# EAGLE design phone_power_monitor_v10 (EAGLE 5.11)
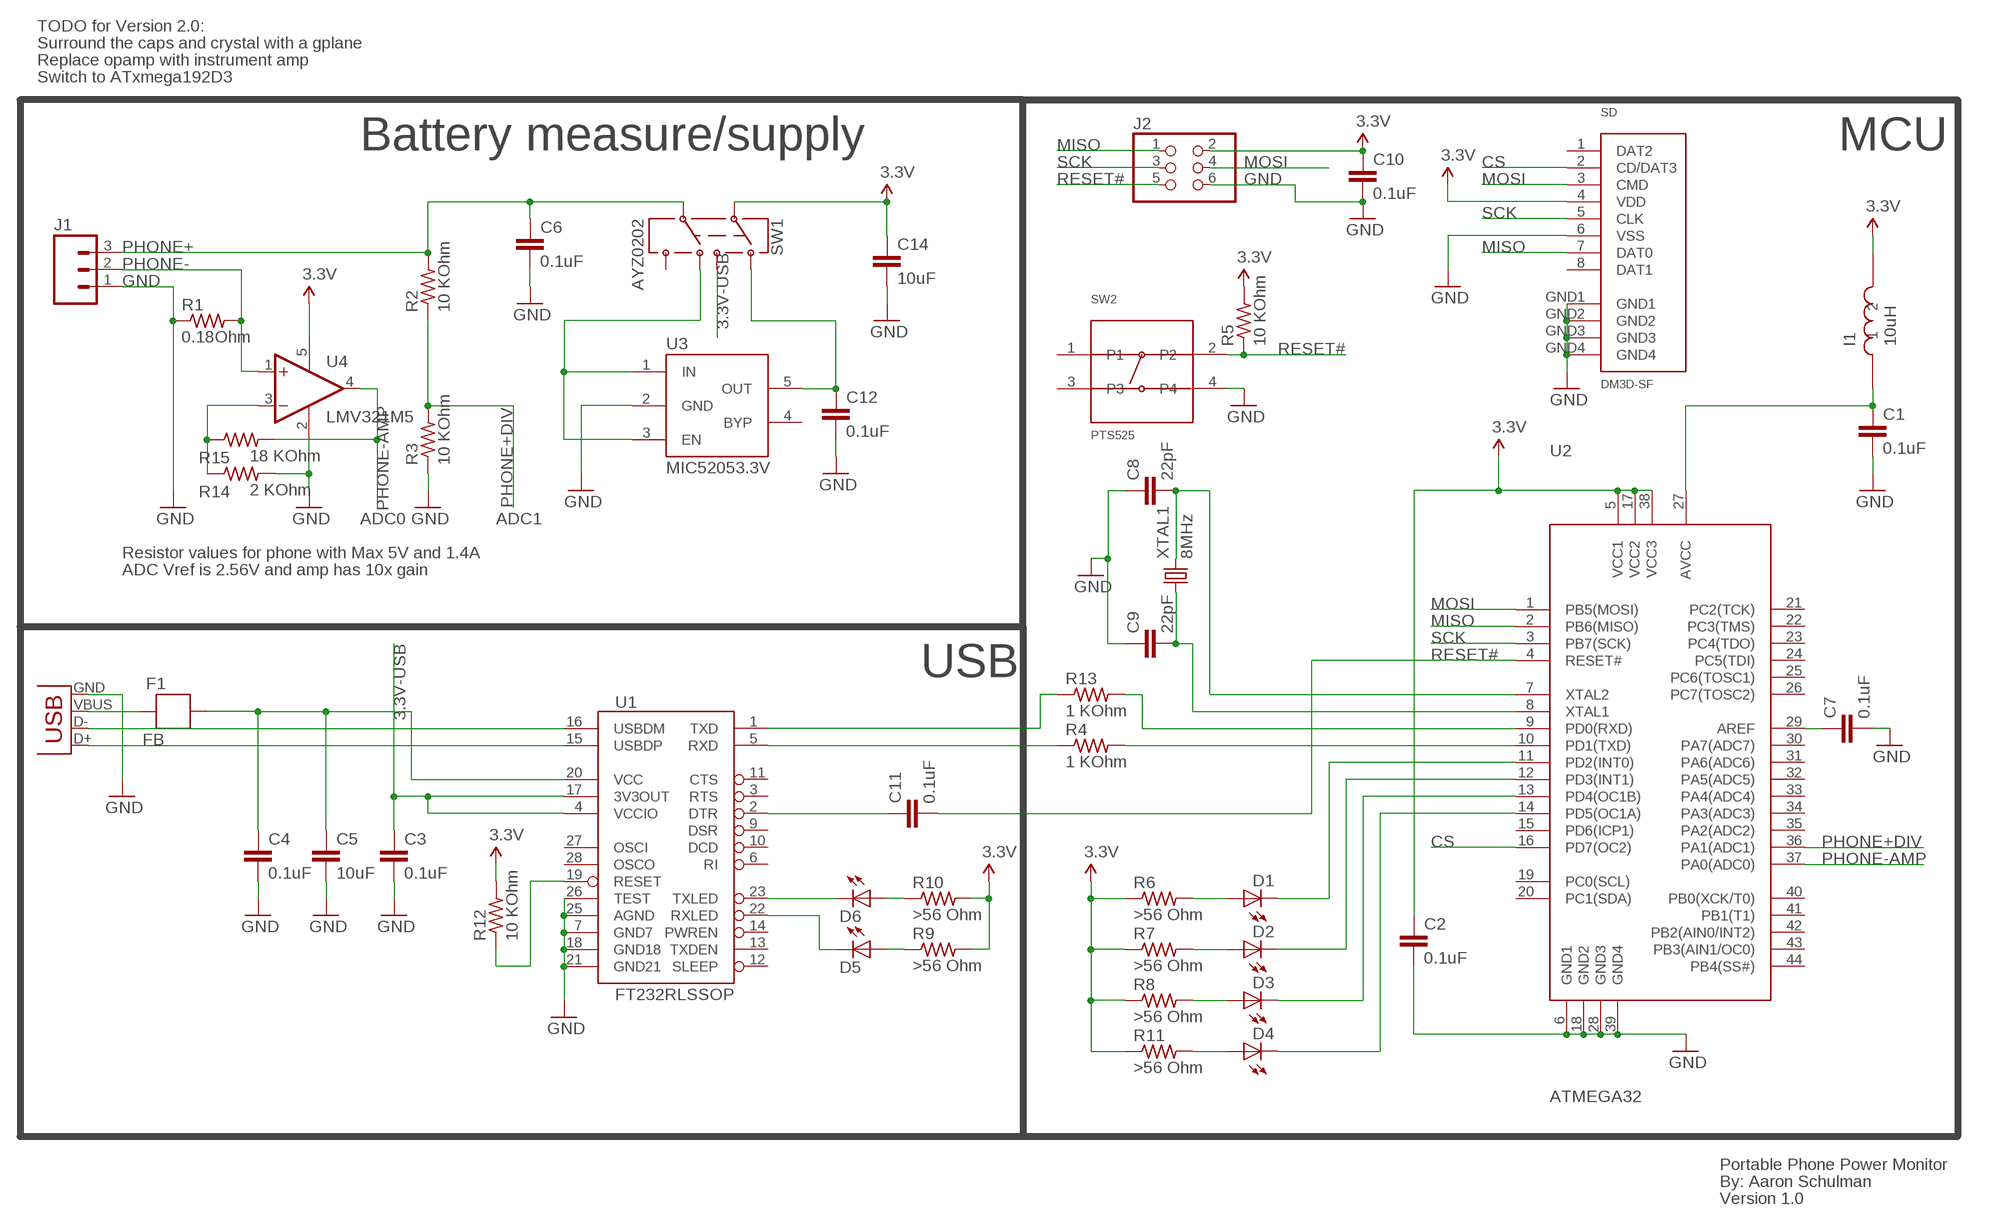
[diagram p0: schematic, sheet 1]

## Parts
C1  0.1uF  CAP0603-CAP  [0603-CAP]
C2  0.1uF  CAP0603-CAP  [0603-CAP]
C3  0.1uF  CAP0603-CAP  [0603-CAP]
C4  0.1uF  CAP0603-CAP  [0603-CAP]
C5  10uF  CAP0603-CAP  [0603-CAP]
C6  0.1uF  CAP0603-CAP  [0603-CAP]
C7  0.1uF  CAP0603-CAP  [0603-CAP]
C8  22pF  CAP0603-CAP  [0603-CAP]
C9  22pF  CAP0603-CAP  [0603-CAP]
C10  0.1uF  CAP0603-CAP  [0603-CAP]
C11  0.1uF  CAP0603-CAP  [0603-CAP]
C12  0.1uF  CAP0603-CAP  [0603-CAP]
C14  10uF  CAP0603-CAP  [0603-CAP]
D1  LED0603  [LED-0603]
D2  LED0603  [LED-0603]
D3  LED0603  [LED-0603]
D4  LED0603  [LED-0603]
D5  LED0603  [LED-0603]
D6  LED0603  [LED-0603]
F1  FB  [0603]
I1  10uH  IHLP-2020CZ-11  [IHLP-2020CZ-11]
J1  M03PTH  [1X03]
J2  PINHD-2X3  [2X03]
R1  0.18Ohm  R-US_R2512  [R2512]
R2  10 KOhm  R-US_R0603  [R0603]
R3  10 KOhm  R-US_R0603  [R0603]
R4  1 KOhm  R-US_R0603  [R0603]
R5  10 KOhm  R-US_R0603  [R0603]
R6  >56 Ohm  R-US_R0603  [R0603]
R7  >56 Ohm  R-US_R0603  [R0603]
R8  >56 Ohm  R-US_R0603  [R0603]
R9  >56 Ohm  R-US_R0603  [R0603]
R10  >56 Ohm  R-US_R0603  [R0603]
R11  >56 Ohm  R-US_R0603  [R0603]
R12  10 KOhm  R-US_R0603  [R0603]
R13  1 KOhm  R-US_R0603  [R0603]
R14  2 KOhm  R-US_R0603  [R0603]
R15  18 KOhm  R-US_R0603  [R0603]
SD  DM3D-SF  [DM3D-SF]
SW1  AYZ0202  [AYZ0202]
SW2  PTS525  [PT525]
U1  FT232RLSSOP  [SSOP28DB]
U2  ATMEGA32  [TQFP-44]
U3  MIC52053.3V  [SOT23-5]
U4  LMV321M5  [SOT23-5]
X1  USBSMD  [USB-MINIB]
XTAL1  8MHz  CRYSTAL10.5X4.8  [CRYSTAL-SMD-10.5X4.8-2PIN]

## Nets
3.3V: C2.1 C10.1 C14.1 I1.2 J2.2 R5.2 R6.1 R7.1 R8.1 R9.2 R10.2 R11.1 R12.2 SD.4(VDD) SW1.2 U2.5(VCC1) U2.17(VCC2) U2.38(VCC3) U4.5(V+)
3.3V-USB: C3.1 SW1.1 U1.4(VCCIO) U1.17(3V3OUT)
CS: SD.2(CD/DAT3) U2.16(PD7(OC2))
D4: D4.C U2.14(PD5(OC1A))
GND: C1.2 C2.2 C3.2 C4.2 C5.2 C6.2 C7.2 C8.1 C9.1 C10.2 C12.2 C14.2 J1.1 J2.6 R1.1 R3.1 R14.2 SD.6(VSS) SD.GND1 SD.GND2 SD.GND3 SD.GND4 SW2.4 U1.7(GND7) U1.18(GND18) U1.21(GND21) U1.25(AGND) U1.26(TEST) U2.6(GND1) U2.18(GND2) U2.28(GND3) U2.39(GND4) U3.2(GND) U4.2(V-) X1.GND
MISO: J2.1 SD.7(DAT0) U2.2(PB6(MISO))
MOSI: J2.4 SD.3(CMD) U2.1(PB5(MOSI))
N$1: C8.2 U2.7(XTAL2) XTAL1.P$2
N$2: C1.1 I1.1 U2.27(AVCC)
N$3: C7.1 U2.29(AREF)
N$4: R14.1 R15.1 U4.3(-IN)
N$5: C11.1 U1.2(DTR)
N$6: D1.A R6.2
N$7: F1.2 X1.VBUS
N$8: C4.1 C5.1 F1.1 U1.20(VCC)
N$9: C9.2 U2.8(XTAL1) XTAL1.P$1
N$10: R4.1 U1.5(RXD)
N$11: R4.2 U2.10(PD1(TXD))
N$12: R13.1 U1.1(TXD)
N$13: R13.2 U2.9(PD0(RXD))
N$14: C12.1 SW1.3 U3.5(OUT)
N$15: D6.C U1.23(TXLED)
N$16: D5.C U1.22(RXLED)
N$17: D2.A R7.2
N$18: D3.A R8.2
N$19: D1.C U2.11(PD2(INT0))
N$20: D4.A R11.2
N$21: D6.A R10.1
N$22: D2.C U2.12(PD3(INT1))
N$23: D3.C U2.13(PD4(OC1B))
N$25: D5.A R9.1
N$26: R12.1 U1.19(RESET)
PHONE+: C6.1 J1.3 R2.2 SW1.5
PHONE+DIV: R2.1 R3.2 U2.36(PA1(ADC1))
PHONE-: J1.2 R1.2 U4.1(+IN)
PHONE-AMP: R15.2 U2.37(PA0(ADC0)) U4.4(OUT)
RESET#: C11.2 J2.5 R5.1 SW2.2 U2.4(RESET#)
SCK: J2.3 SD.5(CLK) U2.3(PB7(SCK))
SWITCH_PHONE+: SW1.6 U3.1(IN) U3.3(EN)
USBDM: U1.16(USBDM) X1.D-
USBDP: U1.15(USBDP) X1.D+
Unconnected: SD.1(DAT2) SD.8(DAT1) SW1.4 SW2.1 SW2.3 U1.3(RTS) U1.6(RI) U1.9(DSR) U1.10(DCD) U1.11(CTS) U1.12(SLEEP) U1.13(TXDEN) U1.14(PWREN) U1.27(OSCI) U1.28(OSCO) U2.15(PD6(ICP1)) U2.19(PC0(SCL)) U2.20(PC1(SDA)) U2.21(PC2(TCK)) U2.22(PC3(TMS)) U2.23(PC4(TDO)) U2.24(PC5(TDI)) U2.25(PC6(TOSC1)) U2.26(PC7(TOSC2)) U2.30(PA7(ADC7)) U2.31(PA6(ADC6)) U2.32(PA5(ADC5)) U2.33(PA4(ADC4)) U2.34(PA3(ADC3)) U2.35(PA2(ADC2)) U2.40(PB0(XCK/T0)) U2.41(PB1(T1)) U2.42(PB2(AIN0/INT2)) U2.43(PB3(AIN1/OC0)) U2.44(PB4(SS#)) U3.4(BYP)

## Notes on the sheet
- TODO for Version 2.0:
- Surround the caps and crystal with a gplane
- Replace opamp with instrument amp
- Switch to ATxmega192D3
- Battery measure/supply | MCU
- ADC0 | ADC1
- Resistor values for phone with Max 5V and 1.4A
- ADC Vref is 2.56V and amp has 10x gain
- USB
- Portable Phone Power Monitor
- By: Aaron Schulman
- Version 1.0

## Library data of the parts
C1-C12 C14 = SparkFun:CAP: Capacitor
D1-D6 = SparkFun:LED: LEDs
F1 = SparkFun:FB
I1 = phone_power_monitor:IHLP-2020CZ-11
J1 = SparkFun:M03: Header 3 Standard 3-pin 0.1" header. Use with straight break away headers (SKU : PRT-00116), right angle break away headers (PRT-00553), swiss pins (PRT-00743), machine pins (PRT-00117), and female headers (PRT-00115). Molex polarized connector foot print use with SKU : PRT-08232 with associated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
J2 = SparkFun:PINHD-2X3: PIN HEADER
R1 = resistor:R-US_: RESISTOR, American symbol
R2-R15 = rcl:R-US_: RESISTOR, American symbol
SD = phone_power_monitor:DM3D-SF
SW1 = SparkFun:AYZ0202: SPDT Slide Switch Simple SMD single-pull double-throw slide switch. Good for less than 350mA power switch, switching UARTs between devices, etc. Spark Fun Electronics SKU : COM-00597
SW2 = phone_power_monitor:PTS525
U1 = SparkFun:FT232RL: USB UART FT232RL 4th Generation USB UART (USB <-> Serial) Controller. Spark Fun Electronics SKU : COM-00650
U2 = phone_power_monitor:ATMEGA32
U3 = phone_power_monitor:MIC5205
U4 = linear:LMV321?*: General Purpose, Low Voltage, Rail-to-Rail Output Operational Amplifiers Source: http://www.national.com/mpf/LM/LMV321.html http://www.national.com/dt/lmv_qual.pdf
X1 = SparkFun:USB: USB Connectors USB-B-PTH is fully proven SKU : PRT-00139 USB-miniB is fully proven SKU : PRT-00587 USB-A-PCB is untested. USB-A-H is throughly reviewed, but untested. Spark Fun Electronics SKU : PRT-00437 USB-B-SMT is throughly reviewed, but untested. Needs silkscreen touching up. USB-A-S has not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
XTAL1 = SparkFun:CRYSTAL: Crystals

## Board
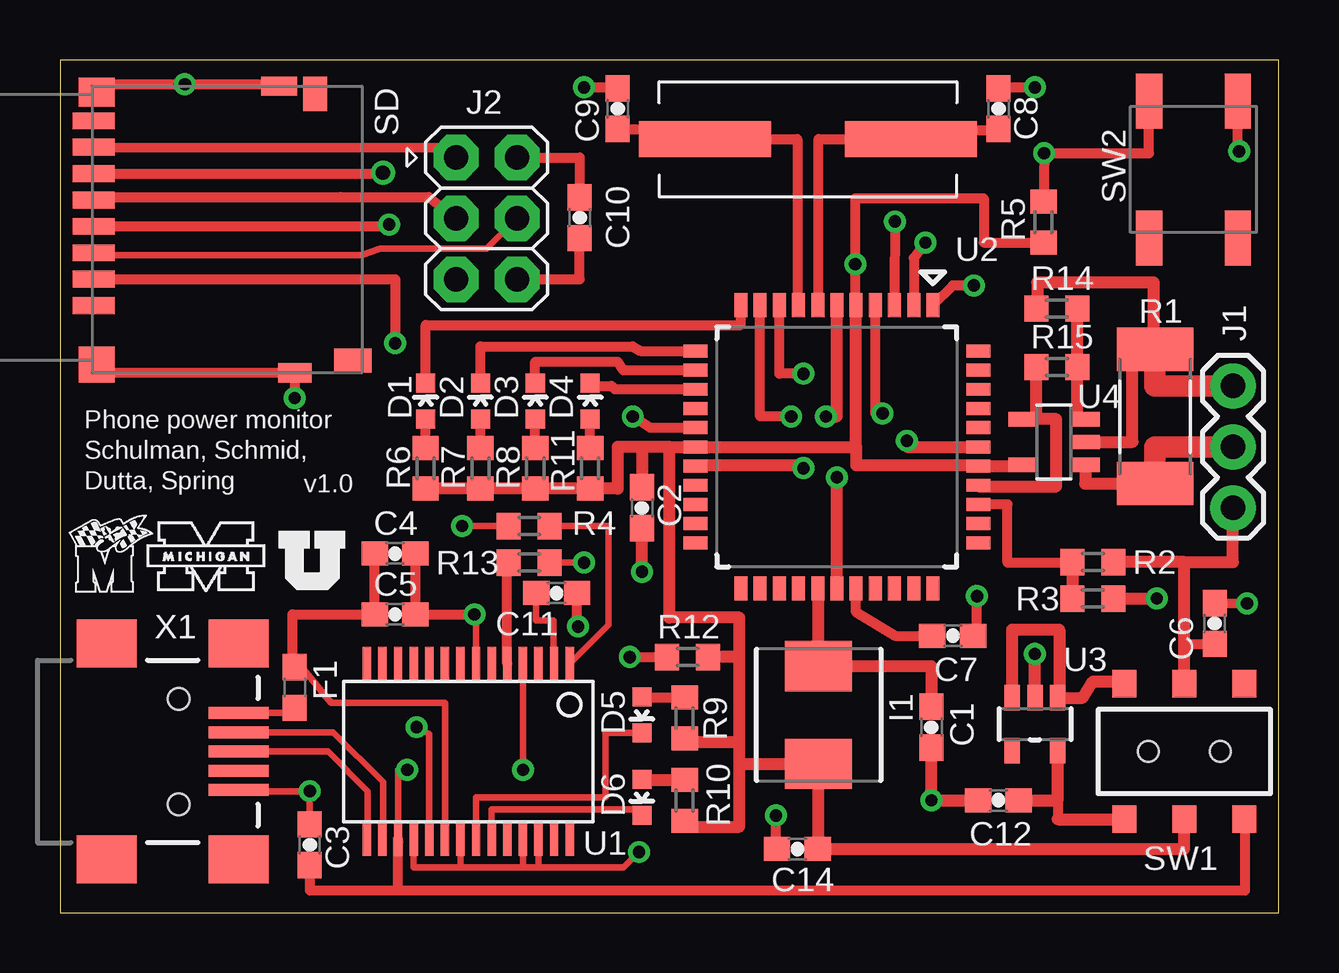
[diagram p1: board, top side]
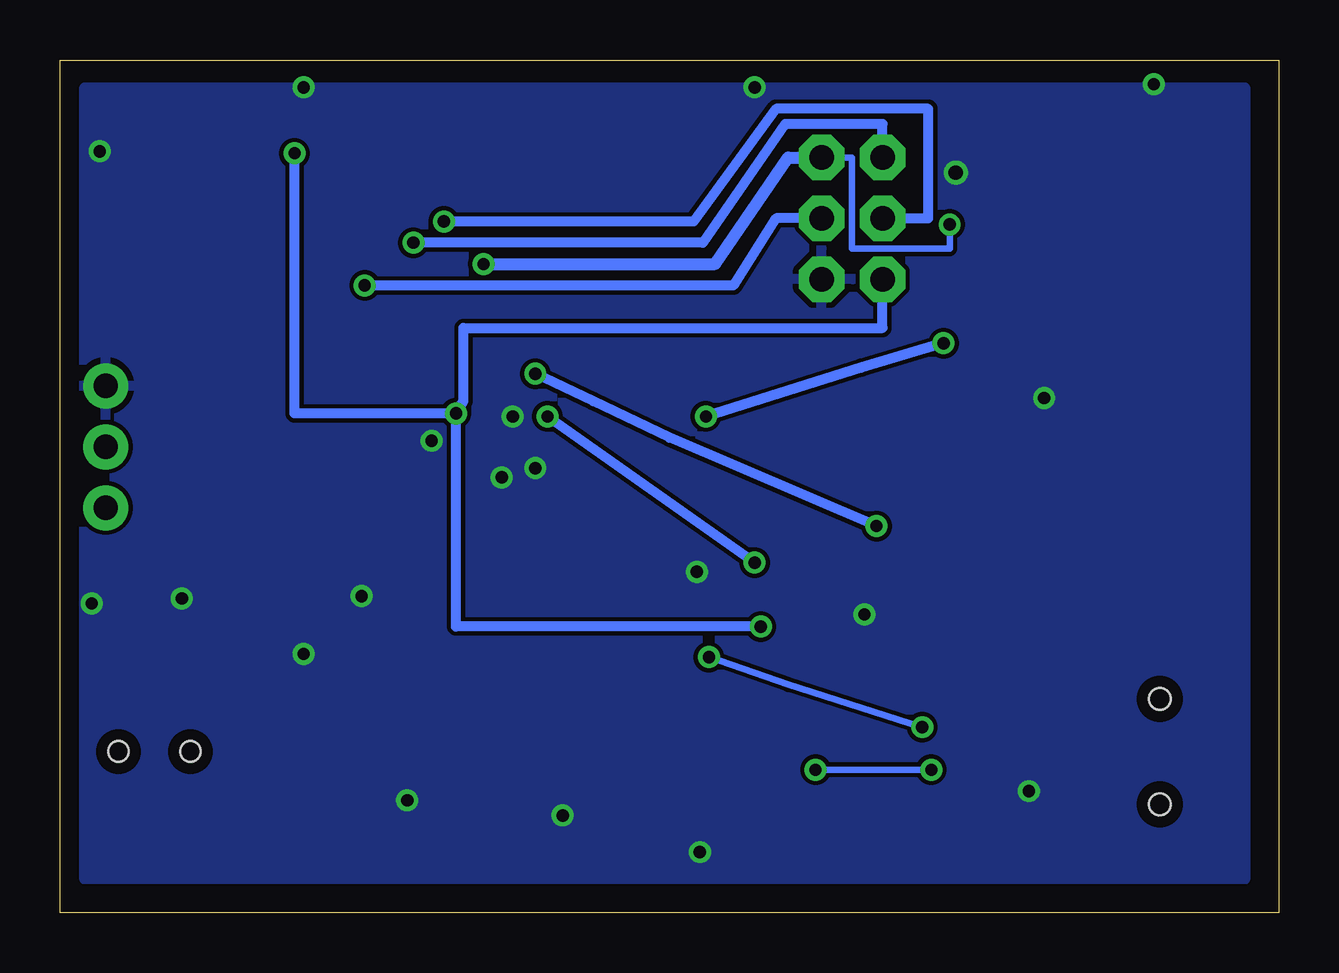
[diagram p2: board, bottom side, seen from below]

Size 50.8 x 35.56 mm. Coordinates in mm from the lower left corner, seen from the top.
Outline: 0,0 50.8,0 50.8,35.56 0,35.56 0,0
Copper layers (1*16): Top 0.0178mm / dielectric 1.4986mm / Bottom 0.0178mm
Design rules "SSC-EAGLE-2Lyr_v1.0.0.3 *": minimum track width 6mil, minimum drill 14mil, track to track 7mil, track to pad 7mil, pad to pad 7mil, via to via 7mil, smd to smd 7mil, copper to edge 20mil, drill to drill 16mil, minimum pad ring 8mil, minimum via ring 8mil, stop-mask expansion 3mil, vias tented up to drill 0mil, thermal gap 10mil

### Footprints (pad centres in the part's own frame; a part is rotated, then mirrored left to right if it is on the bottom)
0603-CAP = smd 1.1 x 1: 1 -0.85,0; 2 0.85,0
LED-0603 = smd 0.8 x 0.8: A 0,-0.75; C 0,0.75
0603 = smd 1.1 x 1: 1 -0.85,0; 2 0.85,0
IHLP-2020CZ-11 = smd 2.1 x 2.79: 1 -2.038,0; 2 2.038,0
1X03 = drill 1.016 pad 1.88 round: 1 0,0; 2 2.54,0; 3 5.08,0
2X03 = drill 1.016 pad 1.88 octagon: 1 -2.54,-1.27; 2 -2.54,1.27; 3 0,-1.27; 4 0,1.27; 5 2.54,-1.27; 6 2.54,1.27
R2512 = smd 1.8 x 3.2: 1 -2.8,0; 2 2.8,0
R0603 = smd 1 x 1.1: 1 -0.85,0; 2 0.85,0
DM3D-SF = smd 0.7 x 1.75: 1 7.7,-0.875; 2 6.6,-0.875; 3 5.5,-0.875; 4 4.4,-0.875; 5 3.3,-0.875; 6 2.2,-0.875; 7 1.1,-0.875; 8 0,-0.875 | smd 0.8 x 1.5: GND1 -1.45,6.85 | smd 0.8 x 1.4: GND2 10.5,7.5 | smd 1.5 x 1.5: GND3 10.15,-0.75 | smd 1.2 x 1.5: GND4 -1.2,-0.75 | smd 1 x 1.55: P$4 10,9.925 | smd 1.45 x 1: P$5 -1.125,8.35
AYZ0202 = smd 1 x 1.15: 1 -2.5,2.825; 2 0,2.825; 3 2.5,2.825; 4 -2.5,-2.825; 5 0,-2.825; 6 2.5,-2.825 | hole 0.85: 1.5,0; -1.5,0
PT525 = smd 2.3 x 1.1: 1 -2.85,1.85; 2 2.85,1.85; 3 -2.85,-1.85; 4 2.85,-1.85
SSOP28DB = smd 0.348 x 1.397: 1 -4.225,-3.656; 2 -3.575,-3.656; 3 -2.925,-3.656; 4 -2.275,-3.656; 5 -1.625,-3.656; 6 -0.975,-3.656; 7 -0.325,-3.656; 8 0.325,-3.656; 9 0.975,-3.656; 10 1.625,-3.656; 11 2.275,-3.656; 12 2.925,-3.656; 13 3.575,-3.656; 14 4.225,-3.656; 15 4.225,3.656; 16 3.575,3.656; 17 2.925,3.656; 18 2.275,3.656; 19 1.625,3.656; 20 0.975,3.656; 21 0.325,3.656; 22 -0.325,3.656; 23 -0.975,3.656; 24 -1.625,3.656; 25 -2.275,3.656; 26 -2.925,3.656; 27 -3.575,3.656; 28 -4.225,3.656
TQFP-44 = smd 1 x 0.54: 1 -5.9,4; 2 -5.9,3.2; 3 -5.9,2.4; 4 -5.9,1.6; 5 -5.9,0.8; 6 -5.9,0; 7 -5.9,-0.8; 8 -5.9,-1.6; 9 -5.9,-2.4; 10 -5.9,-3.2; 11 -5.9,-4; 23 5.9,-4; 24 5.9,-3.2; 25 5.9,-2.4; 26 5.9,-1.6; 27 5.9,-0.8; 28 5.9,0; 29 5.9,0.8; 30 5.9,1.6; 31 5.9,2.4; 32 5.9,3.2; 33 5.9,4 | smd 0.54 x 1: 12 -4,-5.9; 13 -3.2,-5.9; 14 -2.4,-5.9; 15 -1.6,-5.9; 16 -0.8,-5.9; 17 0,-5.9; 18 0.8,-5.9; 19 1.6,-5.9; 20 2.4,-5.9; 21 3.2,-5.9; 22 4,-5.9; 34 4,5.9; 35 3.2,5.9; 36 2.4,5.9; 37 1.6,5.9; 38 0.8,5.9; 39 0,5.9; 40 -0.8,5.9; 41 -1.6,5.9; 42 -2.4,5.9; 43 -3.2,5.9; 44 -4,5.9
SOT23-5 = smd 0.65 x 1.06: 1 0.95,1.1; 2 0,1.1; 3 -0.95,1.1; 4 -0.95,-1.1; 5 0.95,-1.1
SOT23-5' = smd 0.6 x 1.2: 1 -0.95,-1.306; 2 0,-1.306; 3 0.95,-1.306; 4 0.95,1.306; 5 -0.95,1.306
USB-MINIB = smd 2.5 x 0.5: D+ 2.5,0; D- 2.5,0.8; GND 2.5,-1.6; ID 2.5,-0.8; VBUS 2.5,1.6 | smd 2.5 x 2: MTN1 -3,4.5; MTN2 2.5,4.5; MTN3 -3,-4.5; MTN4 2.5,-4.5 | hole 0.9: 0,2.2; 0,-2.2
CRYSTAL-SMD-10.5X4.8-2PIN = smd 5.5 x 1.5: P$1 -4.3,0; P$2 4.3,0

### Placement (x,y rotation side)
C1  36.32,7.75 270 top
C2  24.26,16.89 270 top
C3  10.41,2.84 90 top
C4  13.97,14.99 0 top
C5  13.97,12.45 0 top
C6  48.13,12.06 90 top
C7  37.21,11.56 0 top
C8  39.12,33.53 270 top
C9  23.24,33.53 270 top
C10  21.67,28.98 270 top
C11  20.7,13.34 0 top
C12  39.12,4.7 180 top
C14  30.73,2.67 180 top
D1  15.24,21.34 0 top
D2  17.53,21.34 0 top
D3  19.81,21.34 0 top
D4  22.1,21.34 0 top
D5  24.26,8.26 180 top
D6  24.26,4.83 180 top
F1  9.78,9.4 270 top
I1  31.62,8.26 270 top
J1  48.9,21.97 270 top
J2  17.78,28.96 270 top
R1  45.64,20.7 270 top
R2  43.05,14.63 0 top
R3  43.05,13.11 180 top
R4  19.56,14.61 0 top
R5  41,28.8 270 top
R6  15.24,18.54 90 top
R7  17.53,18.54 90 top
R8  19.81,18.54 90 top
R9  26.04,8.13 270 top
R10  26.04,4.7 270 top
R11  22.1,18.54 90 top
R12  26.16,10.67 0 top
R13  19.56,16.13 180 top
R14  41.55,25.2 180 top
R15  41.55,22.76 180 top
SD  2.29,33.02 270 top
SW1  46.86,6.73 180 top
SW2  47.24,30.99 90 top
U1  17.02,6.73 180 top
U2  32.38,19.43 270 top
U3  40.64,7.87 0 top
U4  LMV321M5  [SOT23-5']  41.43,19.63 90 top
U$1  [UMD_LOGO]  0.25,13.28 0 top
U$2  [UTAH_LOGO]  9.14,13.46 0 top
U$3  [UMICH]  3.56,13.21 0 top
X1  4.95,6.73 0 top
XTAL1  31.18,32.26 0 top

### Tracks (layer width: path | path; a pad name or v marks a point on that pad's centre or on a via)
3.3V  (via drill 0.51)
  Top 0.254: 38.25,18.67 U2.38
  Top 0.279: 26.04,7.11 R9.2 | R10.2 26.04,3.6
  Top 0.406: I1.2 31.58,6.18 | v13.72,28.7 13.34,28.62 SD.4 | C10.1 21.67,31.5 J2.2 | R5.2 38.51,27.95 38.51,29.79 33.15,29.79 v33.15,27.05 33.15,25.33 U2.5 | 40.12,18.63 U4.5
  Top 0.508: SW1.2 46.86,2.67 C14.1 31.58,6.18 | 38.25,18.67 33.19,18.67 33.19,19.43 | 33.19,19.43 U2.5 | 33.19,19.43 U2.17 25.4,19.43 | 25.4,19.43 24.26,19.43 | 24.26,19.43 C2.1 | R6.1 R7.1 R8.1 R11.1 23.24,17.69 23.24,19.43 24.26,19.43 | 28.32,6.22 I1.2 | 25.4,19.43 25.4,12.32 28.32,12.32 28.32,10.67 | 28.32,6.22 28.32,7.11 | 28.32,7.11 28.32,10.67 | 28.32,6.22 28.32,3.6 26.04,3.6 | 28.32,7.11 26.04,7.11 | 28.32,10.67 R12.2 | U2.38 40.12,18.63
  Bottom 0.279: J2.2 17.78,31.5 17.78,27.69 13.72,27.69 v13.72,28.7
  Bottom 0.508: J2.2 20.45,31.5 23.5,27.05 v33.15,27.05
3.3V-USB  (via drill 0.51)
  Top 0.279: U1.17 14.09,5.97 v14.48,5.97 | v19.3,5.97 19.3,10.39 U1.4
  Top 0.406: SW1.1 49.4,3.91 49.4,0.94 14.1,0.94 | 14.1,0.94 14.1,2.95 U1.17 | C3.1 10.41,0.94 14.1,0.94
  Bottom 0.279: v14.48,5.97 v19.3,5.97
CS  (via drill 0.51)
  Top 0.406: SD.2 13.97,26.42 v13.97,23.75 | U2.16 24.6,20.23 v23.88,20.7
  Bottom 0.406: v23.88,20.7 17.4,22.73 v13.97,23.75
D4
  Top 0.406: 22.1,21.97 D4.C 22.09,21.97 22.1,21.97 | U2.14 23.13,21.83 22.99,21.97 22.1,21.97
GND  (via drill 0.51, 0.6)
  Top 0.279: X1.GND 7.25,5.08 v10.41,5.08 C3.2 | 19.29,3.68 U1.25 19.29,1.91 | U1.26 19.94,1.91 | C14.2 29.84,2.67 | U1.18 14.74,1.91 16.69,1.91 | 16.69,1.91 U1.21 | 16.69,1.91 19.29,1.91 | 19.29,1.91 19.94,1.91 | 19.94,1.91 23.5,1.91 v24.13,2.54 | U1.7 17.34,12.5 arc90 v17.27,12.45 | U2.18 26.92,18.67
  Top 0.406: U2.18 26.52,18.67 | 26.92,18.67 26.42,18.67 | v38.23,13.21 38.23,11.85 C7.2 | v40.64,34.42 39.5,34.42 C8.1 | v21.84,34.42 22.73,34.42 C9.1 | 29.84,2.67 v29.84,4.06 | v17.27,12.45 C5.2 C4.2 | SD.GND3 1.54,22.52 SD.GND2 arc90 SD.GND2 v9.78,21.46 | SD.GND4 arc-90 1.79,34.47 1.86,34.54 v5.21,34.54 9.06,34.54 SD.GND1 | 49.09,34.16 SW2.4 49.09,31.75 v49.15,31.75 | C6.2 v49.48,12.9 | SD.6 13.46,30.82 v13.46,30.86 | C10.2 21.67,26.42 J2.6 | 44.7,22.86 45.64,22.86 | R1.1 45.59,23.5
  Top 0.508: R3.1 v45.72,13.11 | U3.2 v40.64,10.79 | C12.2 v36.32,4.7 C1.2 | U2.28 v32.38,18.16 | 26.92,18.67 30.99,18.67 v30.99,18.54 | U2.39 35.31,19.43 v35.31,19.68 | v24.26,14.22 C2.2 | U2.6 32.38,20.7 v31.93,20.7 | U4.2 44.7,19.63 44.7,22.86 | 45.59,23.5 45.59,26.29 40.73,26.29 40.73,25.2 R14.2
  Top 0.889: J1.1 45.64,21.97 45.64,22.86 R1.1
  Bottom 0.406: v49.15,31.75 49.15,31.62
  pour Bottom: 1.4,34.42 1.4,1.4 49.78,1.4 49.78,34.42
MISO  (via drill 0.51)
  Top 0.406: U2.2 35.59,27.3 v36.07,27.94 | SD.7 16,31.91 J2.1
  Bottom 0.406: J2.1 16.51,32.89 20.57,32.89 24,27.94 v36.07,27.94
MOSI  (via drill 0.51)
  Top 0.279: SD.3 1.4,27.56 1.52,27.43 12.57,27.43 13.34,27.7 17.78,27.7 J2.4
  Top 0.406: v38.1,26.16 37.21,26.16 U2.1
  Bottom 0.406: J2.4 20.95,28.96 22.73,26.16 v38.1,26.16
N$1
  Top 0.406: U2.7 31.62,25.37 31.62,32.26 34.29,32.26 | 34.29,32.26 34.29,32.38 | 34.29,32.26 XTAL1.P$2 35.6,32.38 35.56,32.38 35.56,32.64 39.12,32.64 C8.2
N$2
  Top 0.406: 31.62,13.53 U2.27
  Top 0.508: 31.62,13.53 I1.1 36.32,10.29 C1.1
N$3
  Top 0.406: U2.29 33.19,12.54 34.8,11.56 C7.1
N$4
  Top 0.406: U4.3 42.4,20.58
  Top 0.508: 42.4,20.58 R15.1 R14.1
N$5
  Top 0.279: 20.57,10.41 U1.2 20.57,10.39 20.57,12.19 19.85,12.19 C11.1
N$6
  Top 0.406: R6.2 D1.A
N$7
  Top 0.279: X1.VBUS 9.44,8.33 F1.2
N$8
  Top 0.279: U1.20 16.04,8.76 11.3,8.76 9.95,10.41 arc90 F1.1
  Top 0.406: F1.1 arc-90 9.69,10.34 9.69,12.45 C5.1 C4.1
N$9
  Top 0.406: XTAL1.P$1 27.01,32.38 | U2.8 30.73,25.33 30.73,32.26 XTAL1.P$1 | 23.24,32.42 C9.2 26.88,32.68 XTAL1.P$1 | 26.92,32.38 26.88,32.77 XTAL1.P$1
N$10
  Top 0.406: U1.5 18.64,14.92 R4.1
N$11  (via drill 0.51)
  Top 0.279: R4.2 v21.84,14.61
  Top 0.406: v30.48,20.7 29.18,20.7 U2.10
  Bottom 0.406: v21.84,14.61 v30.48,20.7
N$12
  Top 0.279: R13.1 22.86,16.13 22.86,12 U1.1
N$13  (via drill 0.51)
  Top 0.279: v16.76,16.13 R13.2
  Top 0.406: v30.99,22.48 29.98,22.48 U2.9
  Bottom 0.406: v16.76,16.13 25.4,19.81 28.57,21.34 v30.99,22.48
N$14
  Top 0.406: 41.59,4.7 41.59,3.91
  Top 0.508: U3.5 41.59,4.7 C12.1 | 41.59,3.91 SW1.3
N$15
  Top 0.279: U1.23 17.99,4.32 24.26,4.32 D6.C
N$16
  Top 0.279: U1.22 17.34,4.83 22.73,4.83 22.73,7.5 D5.C
N$17
  Top 0.406: R7.2 D2.A
N$18
  Top 0.406: R8.2 D3.A
N$19
  Top 0.406: U2.11 28.39,24.51 15.24,24.51 D1.C
N$20
  Top 0.406: R11.2 D4.A
N$21
  Top 0.406: D6.A 24.26,5.55
  Top 0.508: 24.26,5.55 R10.1
N$22
  Top 0.406: D2.C 17.53,23.62 23.88,23.62 24.19,23.43 U2.12
N$23
  Top 0.406: D3.C 19.81,22.99 23.24,22.99 23.47,22.63 U2.13
N$25
  Top 0.406: R9.1 24.26,8.98 D5.A
N$26  (via drill 0.51)
  Top 0.279: U1.19 15.39,7.47 v14.86,7.75
  Top 0.406: v23.75,10.67 R12.1
  Bottom 0.279: v23.75,10.67 20.45,9.53 v14.86,7.75
PHONE+
  Top 0.406: C6.1 46.86,11.21 46.86,11.3
  Top 0.508: 46.86,14.63 R2.2 | 46.86,14.63 48.9,14.63 J1.3 | SW1.5 46.86,11.3 46.86,14.63
PHONE+DIV
  Top 0.406: U2.36 39.5,17.03 39.5,14.61 42.2,14.61 R2.1
  Top 0.508: R2.1 R3.2
PHONE-
  Top 0.508: U4.1 42.73,17.9 R1.2
  Top 0.889: J1.2 45.64,19.43 R1.2
PHONE-AMP
  Top 0.406: 40.7,20.58 U4.4 | U2.37 38.28,17.78
  Top 0.508: 38.28,17.78 41.53,17.78 41.53,20.58 40.7,20.58 R15.2
RESET#  (via drill 0.51)
  Top 0.406: v34.29,20.83 33.98,20.83 U2.4 | v21.59,11.94 21.55,11.94 C11.2 | R5.1 v41.02,31.67 45.39,31.67 SW2.2
  Bottom 0.406: v41.02,31.67 41.02,20.83 v34.29,20.83 | v21.59,11.94 34.29,11.94 v34.29,20.83 | J2.5 16.51,24.38 33.98,24.38 33.98,21.34 v34.29,20.83
SCK  (via drill 0.51)
  Top 0.406: v34.8,28.83 34.78,25.91 U2.3 | J2.3 15.37,29.84 11.69,29.85 1.54,29.85 arc90 SD.5
  Bottom 0.406: v34.8,28.83 24.38,28.83 20.95,33.53 14.61,33.53 14.61,28.96 J2.3
SWITCH_PHONE+
  Top 0.406: 41.66,8.97 U3.1 | 44.33,9.65 SW1.6
  Top 0.508: U3.3 39.69,11.81 41.66,11.81 41.66,8.97 | U3.1 42.63,8.97 43.05,9.65 44.33,9.65
USBDM
  Top 0.279: X1.D- 11.39,7.53 13.46,5.46 13.46,3.09 U1.16
USBDP
  Top 0.279: X1.D+ 11.18,6.73 12.83,5.08 12.83,3.11 U1.15

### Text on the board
tPlace: Phone power monitor | Schulman, Schmid, | Dutta, Spring | v1.0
